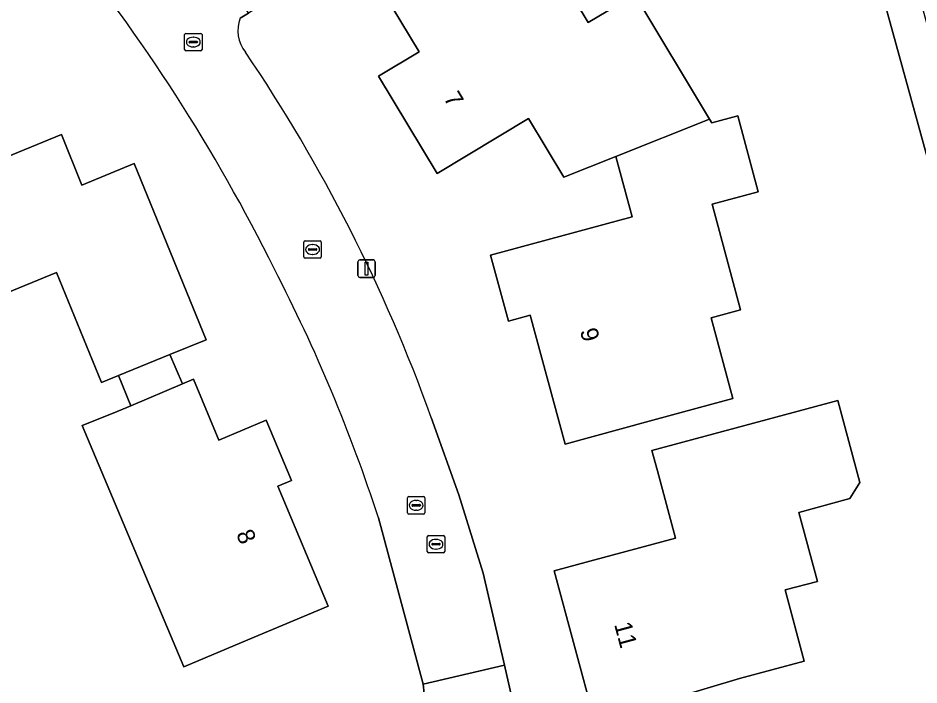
# Model space of a CAD drawing. Extents: x 162156 to 163172, y 378995 to 380779.
# Drawn here: x 162712.5 to 162764.3, y 380109.3 to 380147.6 of the extents above; entities that cross this region are included whole.
import ezdxf

# ---------------------------------------------------------------- set-up
doc = ezdxf.new("R2010")
doc.units = 0
for name, color, linetype in [('IMGEO_Erf', 7, 'Continuous'), ('IMGEO_Kolk', 7, 'Continuous'), ('IMGEO_Lichtmast', 7, 'Continuous'), ('IMGEO_Pand', 7, 'Continuous'), ('IMGEO_Pand_nummerreeks', 7, 'Continuous'), ('IMGEO_Rijbaan_lokaal_open', 7, 'Continuous'), ('IMGEO_Rioolput', 7, 'Continuous'), ('IMGEO_Voetpad_halfverhard', 7, 'Continuous')]:
    doc.layers.add(name, color=color, linetype=linetype)

msp = doc.modelspace()

# ---------------------------------------------------------------- linework, layer by layer
at = {"layer": 'IMGEO_Erf'}
for points in [[(162756.494, 380166.568), (162755.471, 380165.946), (162726.2, 380148.17), (162725.786, 380147.919), (162725.316, 380147.633)], [(162750.429, 380089.805), (162752.191, 380089.762), (162777.588, 380093.171), (162757.756, 380165.253)], [(162742.23, 380152.507), (162745.317, 380147.373), (162747.989, 380148.98), (162752.295, 380141.818), (162752.424, 380141.603), (162753.912, 380142.005), (162755.092, 380137.647), (162752.434, 380136.928), (162754.076, 380130.858), (162752.379, 380130.398), (162753.635, 380125.759), (162751.711, 380125.239), (162748.82, 380124.457), (162743.987, 380123.148), (162741.985, 380130.546), (162740.728, 380130.206), (162739.702, 380133.996), (162747.846, 380136.2), (162746.909, 380139.665), (162743.907, 380138.494), (162741.89, 380141.849), (162736.642, 380138.694), (162733.272, 380144.299), (162735.594, 380145.695), (162732.99, 380150.026)], [(162704.065, 380136.442), (162715.035, 380140.929), (162716.219, 380138.033), (162719.226, 380139.263), (162723.365, 380129.143), (162721.278, 380128.29), (162721.989, 380126.603), (162722.623, 380126.87), (162724.094, 380123.375), (162726.799, 380124.514), (162728.257, 380121.048), (162727.468, 380120.716), (162730.368, 380113.829), (162725.76, 380111.889), (162722.073, 380110.336), (162716.234, 380124.212), (162718.015, 380124.93), (162719.018, 380125.352), (162718.312, 380127.077), (162717.348, 380126.682), (162714.758, 380133.013), (162707.223, 380129.931)], [(162736.289, 380124.676), (162737.884, 380120.234), (162739.273, 380115.723), (162740.499, 380110.432), (162741.124, 380107.734), (162742.484, 380101.867)], [(162735.058, 380105.41), (162735.522, 380106.436), (162735.864, 380107.191), (162735.945, 380108.272), (162735.832, 380109.35), (162733.255, 380118.91)]]:
    msp.add_lwpolyline(points, dxfattribs=at)
msp.add_lwpolyline([(162750.337, 380117.735), (162749.298, 380121.599), (162748.98, 380122.782), (162759.669, 380125.657), (162760.937, 380120.943), (162760.362, 380120.008), (162757.429, 380119.22), (162758.499, 380115.24), (162756.636, 380114.758), (162757.737, 380110.668), (162754.014, 380109.666), (162750.486, 380108.619), (162745.692, 380107.196), (162743.362, 380115.859), (162745.415, 380116.411)], close=True, dxfattribs=at)
for centre, radius, start, end in [((162635.967, 380088.071), 101.851, 26.29955, 39.23242), ((162727.177, 380146.91), 1.996, 158.7658, 218.4327), ((162647.959, 380092.967), 93.85, 19.7474, 34.16386), ((162644.093, 380089.994), 93.734, 17.96835, 27.44666)]:
    msp.add_arc(centre, radius, start, end, dxfattribs=at)
at = {"layer": 'IMGEO_Kolk'}
for p, q in [((162722.118, 380145.825), (162722.118, 380146.677)), ((162722.193, 380146.751), (162723.045, 380146.751)), ((162722.606, 380146.531), (162722.631, 380146.531)), ((162723.119, 380146.677), (162723.119, 380145.825)), ((162722.377, 380146.245), (162722.377, 380146.257)), ((162722.815, 380146.208), (162722.417, 380146.208)), ((162722.42, 380146.294), (162722.818, 380146.294)), ((162722.861, 380146.257), (162722.861, 380146.245)), ((162723.045, 380145.751), (162722.193, 380145.751)), ((162722.629, 380145.971), (162722.604, 380145.971)), ((162728.974, 380133.902), (162728.974, 380134.754)), ((162729.049, 380134.828), (162729.901, 380134.828)), ((162729.975, 380134.754), (162729.975, 380133.902)), ((162729.233, 380134.322), (162729.233, 380134.334)), ((162729.671, 380134.285), (162729.273, 380134.285)), ((162729.276, 380134.371), (162729.674, 380134.371)), ((162729.462, 380134.608), (162729.487, 380134.608)), ((162729.717, 380134.334), (162729.717, 380134.322)), ((162729.901, 380133.828), (162729.049, 380133.828)), ((162729.485, 380134.048), (162729.46, 380134.048)), ((162735.004, 380120.123), (162735.856, 380120.123)), ((162734.929, 380119.197), (162734.929, 380120.049)), ((162735.188, 380119.617), (162735.188, 380119.629)), ((162735.231, 380119.666), (162735.629, 380119.666)), ((162735.417, 380119.903), (162735.442, 380119.903)), ((162735.672, 380119.629), (162735.672, 380119.617)), ((162735.93, 380120.049), (162735.93, 380119.197)), ((162735.856, 380119.123), (162735.004, 380119.123)), ((162735.626, 380119.58), (162735.228, 380119.58)), ((162735.44, 380119.343), (162735.415, 380119.343))]:
    msp.add_line(p, q, dxfattribs=at)
for points in [[(162722.118, 380145.825), (162722.118, 380146.677)], [(162722.193, 380146.751), (162723.045, 380146.751)], [(162723.119, 380146.677), (162723.119, 380145.825)], [(162723.045, 380145.751), (162722.193, 380145.751)], [(162728.974, 380133.902), (162728.974, 380134.754)], [(162729.049, 380134.828), (162729.901, 380134.828)], [(162729.975, 380134.754), (162729.975, 380133.902)], [(162729.901, 380133.828), (162729.049, 380133.828)], [(162735.004, 380120.123), (162735.856, 380120.123)], [(162734.929, 380119.197), (162734.929, 380120.049)], [(162735.93, 380120.049), (162735.93, 380119.197)], [(162735.856, 380119.123), (162735.004, 380119.123)]]:
    msp.add_lwpolyline(points, dxfattribs=at)
for centre, radius, start, end in [((162722.195, 380146.675), 0.0765, 91.552, 178.448), ((162722.195, 380146.675), 0.0765, 91.552, 178.448), ((162723.043, 380146.675), 0.0765, 1.552, 88.448), ((162723.043, 380146.675), 0.0765, 1.552, 88.448), ((162722.417, 380146.254), 0.0403, 85.8775, 175.7526), ((162722.414, 380146.244), 0.0366, 178.938, 274.7102), ((162722.818, 380146.251), 0.043, 264.8664, 352.4533), ((162722.822, 380146.256), 0.0386, 1.7309, 96.639), ((162722.195, 380145.827), 0.0765, 181.552, 268.448), ((162722.195, 380145.827), 0.0765, 181.552, 268.448), ((162723.043, 380145.827), 0.0765, 271.552, 358.448), ((162723.043, 380145.827), 0.0765, 271.552, 358.448), ((162729.051, 380134.752), 0.0765, 91.552, 178.448), ((162729.051, 380134.752), 0.0765, 91.552, 178.448), ((162729.899, 380134.752), 0.0765, 1.552, 88.448), ((162729.899, 380134.752), 0.0765, 1.552, 88.448), ((162729.273, 380134.331), 0.0403, 85.8775, 175.7526), ((162729.27, 380134.321), 0.0366, 178.938, 274.7102), ((162729.674, 380134.328), 0.043, 264.8664, 352.4533), ((162729.678, 380134.333), 0.0386, 1.7309, 96.639), ((162729.051, 380133.904), 0.0765, 181.552, 268.448), ((162729.051, 380133.904), 0.0765, 181.552, 268.448), ((162729.899, 380133.904), 0.0765, 271.552, 358.448), ((162729.899, 380133.904), 0.0765, 271.552, 358.448), ((162735.006, 380120.047), 0.0765, 91.552, 178.448), ((162735.006, 380120.047), 0.0765, 91.552, 178.448), ((162735.854, 380120.047), 0.0765, 1.552, 88.448), ((162735.854, 380120.047), 0.0765, 1.552, 88.448), ((162735.228, 380119.626), 0.0403, 85.8775, 175.7526), ((162735.225, 380119.616), 0.0366, 178.938, 274.7102), ((162735.629, 380119.623), 0.043, 264.8664, 352.4533), ((162735.633, 380119.628), 0.0386, 1.7309, 96.639), ((162735.006, 380119.199), 0.0765, 181.552, 268.448), ((162735.006, 380119.199), 0.0765, 181.552, 268.448), ((162735.854, 380119.199), 0.0765, 271.552, 358.448), ((162735.854, 380119.199), 0.0765, 271.552, 358.448)]:
    msp.add_arc(centre, radius, start, end, dxfattribs=at)
for centre, major_axis, ratio, start_param, end_param in [((162722.605, 380146.251), (-0.387, 0.002), 0.722429, 4.712389, 7.853982), ((162722.63, 380146.251), (-0.39, 0.002), 0.717154, 1.570796, 4.712389), ((162729.461, 380134.328), (-0.387, 0.002), 0.722429, 4.712389, 7.853982), ((162729.486, 380134.328), (-0.39, 0.002), 0.717154, 1.570796, 4.712389), ((162735.416, 380119.623), (-0.387, 0.002), 0.722429, 4.712389, 7.853982), ((162735.441, 380119.623), (-0.39, 0.002), 0.717154, 1.570796, 4.712389)]:
    msp.add_ellipse(centre, major_axis=major_axis, ratio=ratio, start_param=start_param, end_param=end_param, dxfattribs=at)
at = {"layer": 'IMGEO_Lichtmast'}
for p, q in [((162732.08, 380132.828), (162732.08, 380133.628)), ((162732.08, 380133.628), (162732.08, 380132.828)), ((162732.18, 380133.728), (162732.97, 380133.728)), ((162732.97, 380133.728), (162732.18, 380133.728)), ((162733.07, 380133.628), (162733.07, 380132.828)), ((162733.07, 380132.828), (162733.07, 380133.628)), ((162732.97, 380132.728), (162732.18, 380132.728)), ((162732.18, 380132.728), (162732.97, 380132.728))]:
    msp.add_line(p, q, dxfattribs=at)
msp.add_lwpolyline([(162732.5, 380133.603), (162732.65, 380133.603), (162732.65, 380132.853), (162732.5, 380132.853), (162732.5, 380133.603)], dxfattribs=at)
for centre, start, end in [((162732.18, 380133.628), 90, 180), ((162732.18, 380133.628), 90, 180), ((162732.97, 380133.628), 0, 90), ((162732.97, 380133.628), 360, 90), ((162732.18, 380132.828), 180, 270), ((162732.18, 380132.828), 180, 270), ((162732.97, 380132.828), 270, 0), ((162732.97, 380132.828), 270, 0)]:
    msp.add_arc(centre, 0.1, start, end, dxfattribs=at)
at = {"layer": 'IMGEO_Pand'}
for points in [[(162752.295, 380141.818), (162747.989, 380148.98), (162745.317, 380147.373), (162742.23, 380152.507), (162738.89, 380150.499), (162737.532, 380152.757), (162737.276, 380152.603), (162732.99, 380150.026), (162735.594, 380145.695), (162733.272, 380144.299), (162736.642, 380138.694), (162741.89, 380141.849), (162743.907, 380138.494), (162746.909, 380139.665)], [(162755.092, 380137.647), (162753.912, 380142.005), (162752.424, 380141.603), (162752.295, 380141.818), (162746.909, 380139.665), (162747.846, 380136.2), (162739.702, 380133.996), (162740.728, 380130.206), (162741.985, 380130.546), (162743.987, 380123.148), (162748.82, 380124.457), (162751.711, 380125.239), (162753.635, 380125.759), (162752.379, 380130.398), (162754.076, 380130.858), (162752.434, 380136.928)], [(162714.758, 380133.013), (162717.348, 380126.682), (162718.312, 380127.077), (162718.738, 380127.251), (162721.278, 380128.29), (162723.365, 380129.143), (162719.226, 380139.263), (162716.219, 380138.033), (162715.035, 380140.929), (162704.065, 380136.442), (162705.263, 380133.513), (162701.832, 380132.11), (162703.725, 380127.483), (162704.256, 380126.184), (162708.11, 380127.761), (162707.223, 380129.931)], [(162721.278, 380128.29), (162718.738, 380127.251), (162718.312, 380127.077), (162719.018, 380125.352), (162721.989, 380126.603)], [(162727.468, 380120.716), (162728.257, 380121.048), (162726.799, 380124.514), (162724.094, 380123.375), (162722.623, 380126.87), (162721.989, 380126.603), (162719.018, 380125.352), (162718.015, 380124.93), (162716.234, 380124.212), (162722.073, 380110.336), (162725.76, 380111.889), (162730.368, 380113.829)], [(162749.298, 380121.599), (162750.337, 380117.735), (162745.415, 380116.411), (162743.362, 380115.859), (162745.692, 380107.196), (162750.486, 380108.619), (162754.014, 380109.666), (162757.737, 380110.668), (162756.636, 380114.758), (162758.499, 380115.24), (162757.429, 380119.22), (162760.362, 380120.008), (162760.937, 380120.943), (162759.669, 380125.657), (162748.98, 380122.782)]]:
    msp.add_lwpolyline(points, close=True, dxfattribs=at)
at = {"layer": 'IMGEO_Rijbaan_lokaal_open'}
for points in [[(162725.316, 380147.633), (162725.786, 380147.919), (162724.708, 380149.722), (162724.053, 380150.818)], [(162733.255, 380118.91), (162735.832, 380109.35), (162740.499, 380110.432), (162739.273, 380115.723), (162737.884, 380120.234), (162736.289, 380124.676)]]:
    msp.add_lwpolyline(points, dxfattribs=at)
msp.add_lwpolyline([(162735.522, 380106.436), (162741.124, 380107.734), (162740.499, 380110.432), (162735.832, 380109.35), (162735.945, 380108.272), (162735.864, 380107.191)], close=True, dxfattribs=at)
for centre, radius, start, end in [((162635.967, 380088.071), 101.851, 26.29955, 39.23242), ((162727.177, 380146.91), 1.996, 158.7658, 218.4327), ((162647.959, 380092.967), 93.85, 19.7474, 34.16386), ((162644.093, 380089.994), 93.734, 17.96835, 27.44666)]:
    msp.add_arc(centre, radius, start, end, dxfattribs=at)
at = {"layer": 'IMGEO_Rioolput'}
for p, q in [((162736.067, 380116.963), (162736.067, 380117.815)), ((162736.142, 380117.889), (162736.994, 380117.889)), ((162736.555, 380117.669), (162736.58, 380117.669)), ((162737.068, 380117.815), (162737.068, 380116.963)), ((162736.326, 380117.383), (162736.326, 380117.395)), ((162736.764, 380117.346), (162736.366, 380117.346)), ((162736.369, 380117.432), (162736.767, 380117.432)), ((162736.578, 380117.109), (162736.553, 380117.109)), ((162736.81, 380117.395), (162736.81, 380117.383)), ((162736.994, 380116.889), (162736.142, 380116.889))]:
    msp.add_line(p, q, dxfattribs=at)
for points in [[(162736.067, 380116.963), (162736.067, 380117.815)], [(162736.142, 380117.889), (162736.994, 380117.889)], [(162737.068, 380117.815), (162737.068, 380116.963)], [(162736.994, 380116.889), (162736.142, 380116.889)]]:
    msp.add_lwpolyline(points, dxfattribs=at)
for centre, radius, start, end in [((162736.144, 380117.813), 0.0765, 91.552, 178.448), ((162736.144, 380117.813), 0.0765, 91.552, 178.448), ((162736.992, 380117.813), 0.0765, 1.552, 88.448), ((162736.992, 380117.813), 0.0765, 1.552, 88.448), ((162736.366, 380117.392), 0.0403, 85.8775, 175.7526), ((162736.363, 380117.382), 0.0366, 178.938, 274.7102), ((162736.767, 380117.389), 0.043, 264.8664, 352.4533), ((162736.771, 380117.394), 0.0386, 1.7309, 96.639), ((162736.144, 380116.965), 0.0765, 181.552, 268.448), ((162736.144, 380116.965), 0.0765, 181.552, 268.448), ((162736.992, 380116.965), 0.0765, 271.552, 358.448), ((162736.992, 380116.965), 0.0765, 271.552, 358.448)]:
    msp.add_arc(centre, radius, start, end, dxfattribs=at)
for centre, major_axis, ratio, start_param, end_param in [((162736.554, 380117.389), (-0.387, 0.002), 0.722429, 4.712389, 7.853982), ((162736.579, 380117.389), (-0.39, 0.002), 0.717154, 1.570796, 4.712389)]:
    msp.add_ellipse(centre, major_axis=major_axis, ratio=ratio, start_param=start_param, end_param=end_param, dxfattribs=at)
at = {"layer": 'IMGEO_Voetpad_halfverhard'}
msp.add_lwpolyline([(162757.756, 380165.253), (162777.588, 380093.171), (162779.588, 380093.439), (162758.215, 380171.258), (162756.789, 380172.742), (162753.063, 380176.112), (162750.127, 380178.223), (162742.813, 380182.703), (162737.024, 380185.747), (162731.803, 380187.774)], dxfattribs=at)

# ---------------------------------------------------------------- texts
at = {"layer": 'IMGEO_Pand_nummerreeks'}
for s, rotation, p in [('7', 301.0163, (162736.974, 380143.031)), ('9', 285.1431, (162744.833, 380129.666)), ('8', 292.8379, (162725.061, 380117.982)), ('11', 285.0514, (162746.799, 380112.783))]:
    msp.add_text(s, height=1, rotation=rotation, dxfattribs=at).set_placement(p)

doc.saveas('drawing.dxf')
